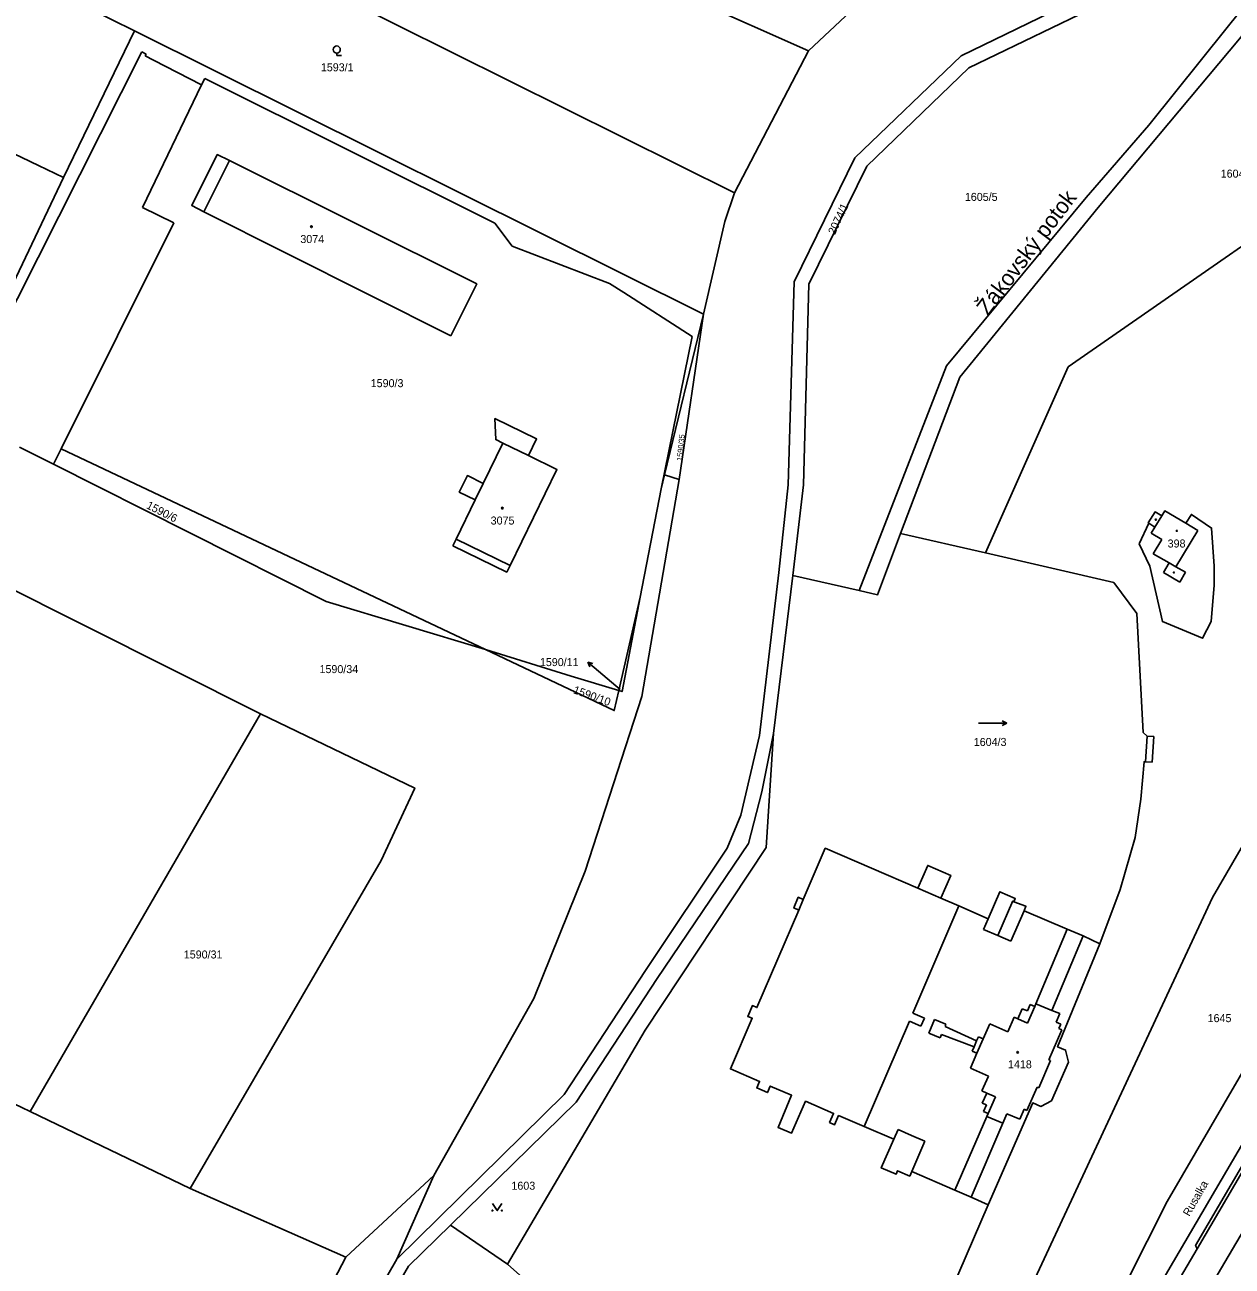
# Model space of a CAD drawing. Extents: x -679220 to -673243, y -1075091 to -1066557.
# Drawn here: x -677626.7 to -677370.2, y -1071876.4 to -1071612.6 of the extents above; entities that cross this region are included whole.
import ezdxf

# ---------------------------------------------------------------- set-up
doc = ezdxf.new("R2010")
doc.units = 0
for name, color, linetype in [('Hranice parcel', 7, 'Continuous'), ('Parcelní čísla', 7, 'Continuous'), ('Pop  PČ popisy', 7, 'Continuous'), ('Vnitřní kresba', 7, 'Continuous'), ('Značky budov', 7, 'Continuous'), ('Značky kultur', 7, 'Continuous')]:
    doc.layers.add(name, color=color, linetype=linetype)

msp = doc.modelspace()

# ---------------------------------------------------------------- linework, layer by layer
at = {"layer": 'Hranice parcel'}
for p, q in [((-677475.97, -1071648.33), (-677611.33, -1071580.93)), ((-677603.41, -1071613.91), (-677623.32, -1071603.99)), ((-677460.19, -1071618.11), (-677484.77, -1071607.17)), ((-677451.21, -1071609.71), (-677460.19, -1071618.11)), ((-677603.41, -1071613.91), (-677618.5, -1071645.05)), ((-677482.55, -1071674.1), (-677603.41, -1071613.91)), ((-677618.5, -1071645.05), (-677675.7, -1071617.62)), ((-677475.97, -1071648.33), (-677460.19, -1071618.11)), ((-677618.5, -1071645.05), (-677641.36, -1071692.91)), ((-677490.81, -1071708.2), (-677482.55, -1071674.1)), ((-677487.67, -1071709.23), (-677482.55, -1071674.1)), ((-677627.85, -1071702.34), (-677620.62, -1071705.96)), ((-677487.67, -1071709.23), (-677490.81, -1071708.2)), ((-677440.64, -1071720.72), (-677422.65, -1071724.8)), ((-677576.6, -1071759.04), (-677642.42, -1071725.99)), ((-677463.55, -1071729.64), (-677467.68, -1071763.17)), ((-677449.46, -1071732.84), (-677463.55, -1071729.64)), ((-677500.52, -1071754.07), (-677495.95, -1071734.2)), ((-677576.6, -1071759.04), (-677625.55, -1071843.55)), ((-677625.55, -1071843.55), (-677690.35, -1071812.12)), ((-677591.59, -1071859.9), (-677625.55, -1071843.55)), ((-677388.37, -1071885.06), (-677364.82, -1071844.92)), ((-677539.81, -1071857.13), (-677558.48, -1071874.5)), ((-677547.65, -1071874.9), (-677539.81, -1071857.13)), ((-677558.48, -1071874.5), (-677591.59, -1071859.9)), ((-677536.24, -1071867.65), (-677524.13, -1071875.98))]:
    msp.add_line(p, q, dxfattribs=at)
for points in [[(-677547.65, -1071874.9), (-677512.13, -1071839.9), (-677494.84, -1071813.59), (-677477.52, -1071787.54), (-677474.59, -1071780.52), (-677470.62, -1071763.59), (-677466.53, -1071728.98), (-677464.55, -1071710.33), (-677463.26, -1071667.2), (-677450.4, -1071640.86), (-677427.79, -1071619.2), (-677404.1, -1071607.74), (-677392.74, -1071599.33), (-677364.3, -1071568.01), (-677352.33, -1071547.38), (-677353.42, -1071517.27), (-677364.45, -1071472.8), (-677366.9, -1071460.72), (-677361.99, -1071451.74), (-677335.82, -1071408.46), (-677315.48, -1071374.36), (-677305.32, -1071362.98)], [(-677361.41, -1071471.95), (-677350.43, -1071516.86), (-677349.56, -1071533.03), (-677349.29, -1071547.83), (-677361.83, -1071569.86), (-677390.7, -1071601.66), (-677402.66, -1071610.43), (-677426.13, -1071621.73), (-677447.8, -1071642.64), (-677460.12, -1071667.74), (-677461.31, -1071710.35), (-677463.55, -1071729.64)], [(-677449.46, -1071732.84), (-677430.89, -1071685.08), (-677401.23, -1071649.29), (-677387.93, -1071633.95), (-677371.26, -1071613.2), (-677344.18, -1071579.41), (-677335.48, -1071540.9), (-677322.24, -1071482.13)], [(-677337.68, -1071566.95), (-677341.37, -1071581.96), (-677368.67, -1071615.55), (-677398.69, -1071651.4), (-677428.04, -1071687.44), (-677440.64, -1071720.72)], [(-677422.65, -1071724.8), (-677405.05, -1071685.3), (-677334.85, -1071636.58), (-677327.31, -1071627.01)], [(-677536.2, -1071678.67), (-677588.68, -1071652.34), (-677591.25, -1071651), (-677585.84, -1071640.17), (-677583.21, -1071641.44), (-677530.69, -1071667.67), (-677536.2, -1071678.67)], [(-677482.55, -1071674.1), (-677478.02, -1071654.43), (-677475.97, -1071648.33)], [(-677535.78, -1071723.31), (-677535.1, -1071721.91), (-677531.01, -1071713.55), (-677534.43, -1071711.88), (-677532.67, -1071708.39), (-677529.3, -1071710.04), (-677525.13, -1071701.5), (-677526.66, -1071700.75), (-677526.82, -1071696.29), (-677518, -1071700.6), (-677519.73, -1071704.13), (-677513.66, -1071707.1), (-677523.63, -1071727.51), (-677524.31, -1071728.91), (-677535.78, -1071723.31)], [(-677620.62, -1071705.96), (-677618.98, -1071702.68), (-677528.86, -1071745.38)], [(-677620.62, -1071705.96), (-677562.65, -1071735.14), (-677528.86, -1071745.38)], [(-677539.81, -1071857.13), (-677518.6, -1071819.49), (-677507.69, -1071792.48), (-677495.6, -1071755.32), (-677487.67, -1071709.23)], [(-677495.95, -1071734.2), (-677491.54, -1071711.22), (-677490.81, -1071708.2)], [(-677389.96, -1071722.91), (-677387.74, -1071727.63), (-677385.04, -1071739.4), (-677376.49, -1071742.94), (-677374.66, -1071739.36), (-677374.06, -1071731.64), (-677374.05, -1071727.62), (-677374.6, -1071719.54), (-677378.88, -1071716.64), (-677380.07, -1071718.51), (-677384.53, -1071715.89), (-677385.16, -1071716.93), (-677386.58, -1071716.1), (-677388.04, -1071718.46), (-677387.94, -1071718.52), (-677389.96, -1071722.91)], [(-677440.64, -1071720.72), (-677445.56, -1071733.72), (-677449.46, -1071732.84)], [(-677398.31, -1071807.87), (-677394.02, -1071796.32), (-677390.81, -1071785.3), (-677389.64, -1071777.13), (-677388.92, -1071769.19), (-677388.63, -1071769.2), (-677388.25, -1071763.76), (-677389.12, -1071762.96), (-677390.46, -1071737.69), (-677395.38, -1071731.13), (-677422.65, -1071724.8)], [(-677495.95, -1071734.2), (-677499.82, -1071754.28), (-677500.52, -1071754.07)], [(-677429.99, -1071917.37), (-677374.41, -1071798.07), (-677357.92, -1071769.61), (-677336.34, -1071740.8)], [(-677528.86, -1071745.38), (-677501.5, -1071758.34), (-677500.52, -1071754.07)], [(-677528.86, -1071745.38), (-677510.63, -1071750.99), (-677500.52, -1071754.07)], [(-677319.11, -1071756.26), (-677333.59, -1071777.09), (-677353.45, -1071810.1), (-677384.02, -1071862.66), (-677396.73, -1071887.8), (-677406.87, -1071911.8), (-677407.41, -1071916.34)], [(-677591.59, -1071859.9), (-677551.02, -1071790.19), (-677543.85, -1071774.81), (-677576.6, -1071759.04)], [(-677467.68, -1071763.17), (-677470.11, -1071775.61), (-677472.96, -1071786.54), (-677492.39, -1071815.25), (-677509.58, -1071841.54), (-677536.24, -1071867.65)], [(-677524.13, -1071875.98), (-677494.9, -1071826.26), (-677469.21, -1071787.42), (-677467.68, -1071763.17)], [(-677398.31, -1071807.87), (-677401.9, -1071806.2), (-677405.29, -1071804.76), (-677414.42, -1071800.86), (-677414.02, -1071799.92), (-677416.57, -1071798.97), (-677416.29, -1071798.24), (-677419.54, -1071796.82), (-677422.06, -1071802.6), (-677428.26, -1071799.84), (-677432.11, -1071798.18), (-677430.01, -1071793.36), (-677434.9, -1071791.21), (-677437, -1071796.07), (-677456.66, -1071787.59), (-677461.32, -1071798.45), (-677462.39, -1071797.99), (-677463.36, -1071800.25), (-677462.29, -1071800.7), (-677471.19, -1071821.43), (-677472.13, -1071821.02), (-677473.11, -1071823.31), (-677472.17, -1071823.71), (-677476.8, -1071834.48), (-677470.62, -1071837.14), (-677471.22, -1071838.51), (-677468.93, -1071839.49), (-677468.34, -1071838.12), (-677463.8, -1071840.08), (-677466.68, -1071846.9), (-677463.83, -1071848.13), (-677460.85, -1071841.35), (-677454.9, -1071843.92), (-677455.74, -1071845.83), (-677454.67, -1071846.32), (-677453.83, -1071844.38), (-677448.4, -1071846.72), (-677442.06, -1071849.38), (-677444.77, -1071855.51), (-677441.6, -1071856.84), (-677441.28, -1071856.12), (-677438.72, -1071857.23), (-677438.3, -1071856.27), (-677429.1, -1071860.26), (-677425.69, -1071861.73), (-677422.03, -1071863.33)], [(-677422.03, -1071863.33), (-677412.57, -1071841.7), (-677410.84, -1071842.45), (-677408.59, -1071841.23), (-677405, -1071833.07), (-677405.59, -1071830.46), (-677407.32, -1071829.75), (-677398.31, -1071807.87)], [(-677362.83, -1071846.09), (-677378, -1071871.97), (-677377.64, -1071872.67)], [(-677377.64, -1071872.67), (-677366.73, -1071854.04), (-677361.12, -1071857.35), (-677362.14, -1071859.08), (-677349.2, -1071866.71), (-677350.73, -1071869.37), (-677348.57, -1071870.58), (-677352.24, -1071876.83), (-677354.18, -1071875.7), (-677359.9, -1071885.41), (-677365.52, -1071882.11), (-677358.68, -1071870.47), (-677366.2, -1071866.05), (-677374.1, -1071879.52)], [(-677446.61, -1071915.3), (-677431.42, -1071885.01), (-677422.03, -1071863.33)], [(-677536.24, -1071867.65), (-677545.18, -1071876.41), (-677551.26, -1071886.91), (-677551.95, -1071896.52), (-677549, -1071898.42), (-677557.64, -1071899.41)], [(-677374.1, -1071879.52), (-677376.27, -1071883.23), (-677381.89, -1071879.93), (-677377.64, -1071872.67)], [(-677558.48, -1071874.5), (-677562.8, -1071882.76), (-677569.64, -1071895.54), (-677576, -1071917.67)], [(-677557.64, -1071899.41), (-677554, -1071885.85), (-677547.65, -1071874.9)], [(-677446.61, -1071915.3), (-677488.59, -1071898.31), (-677490.88, -1071897.09), (-677520.24, -1071879.43), (-677524.13, -1071875.98)]]:
    msp.add_lwpolyline(points, dxfattribs=at)
at = {"layer": 'Pop  PČ popisy'}
for p, q in [((-677504.8, -1071749.96), (-677507.1, -1071748.03)), ((-677507.1, -1071748.03), (-677506.01, -1071748.29)), ((-677507.1, -1071748.03), (-677506.65, -1071749.06)), ((-677500.22, -1071753.85), (-677504.8, -1071749.96))]:
    msp.add_line(p, q, dxfattribs=at)
at = {"layer": 'Vnitřní kresba'}
for p, q in [((-677601.83, -1071618.35), (-677639.79, -1071693.55)), ((-677600.95, -1071618.81), (-677601.83, -1071618.35)), ((-677601.13, -1071619.17), (-677600.95, -1071618.81)), ((-677599.35, -1071620.09), (-677601.13, -1071619.17)), ((-677589.14, -1071625.39), (-677599.35, -1071620.09)), ((-677589.14, -1071625.39), (-677601.68, -1071651.45)), ((-677588.49, -1071624.04), (-677589.14, -1071625.39)), ((-677526.82, -1071654.76), (-677588.49, -1071624.04)), ((-677588.68, -1071652.34), (-677583.21, -1071641.44)), ((-677601.68, -1071651.45), (-677595.02, -1071654.66)), ((-677595.02, -1071654.66), (-677618.98, -1071702.68)), ((-677523.19, -1071659.61), (-677526.82, -1071654.76)), ((-677502.49, -1071667.57), (-677523.19, -1071659.61)), ((-677499.45, -1071669.45), (-677502.49, -1071667.57)), ((-677484.96, -1071678.85), (-677499.45, -1071669.45)), ((-677484.96, -1071678.85), (-677491.54, -1071711.22)), ((-677525.13, -1071701.5), (-677519.73, -1071704.13)), ((-677529.3, -1071710.04), (-677531.01, -1071713.55)), ((-677386.62, -1071719.33), (-677385.16, -1071716.93)), ((-677387.94, -1071718.52), (-677386.62, -1071719.33)), ((-677386.62, -1071719.33), (-677387.41, -1071720.62)), ((-677387.41, -1071720.62), (-677385.15, -1071721.99)), ((-677382.2, -1071727.77), (-677377.48, -1071720.03)), ((-677380.07, -1071718.51), (-677377.48, -1071720.03)), ((-677535.1, -1071721.91), (-677523.63, -1071727.51)), ((-677385.15, -1071721.99), (-677386.97, -1071725.03)), ((-677383.62, -1071726.95), (-677386.97, -1071725.03)), ((-677384.83, -1071729), (-677383.62, -1071726.95)), ((-677382.2, -1071727.77), (-677383.62, -1071726.95)), ((-677380.1, -1071728.93), (-677382.2, -1071727.77)), ((-677381.35, -1071731.05), (-677384.83, -1071729)), ((-677380.1, -1071728.93), (-677381.35, -1071731.05)), ((-677388.25, -1071763.76), (-677386.84, -1071763.86)), ((-677386.84, -1071763.86), (-677387.22, -1071769.26)), ((-677387.22, -1071769.26), (-677388.63, -1071769.2)), ((-677437, -1071796.07), (-677432.11, -1071798.18)), ((-677461.32, -1071798.45), (-677462.29, -1071800.7)), ((-677420.01, -1071806.14), (-677416.82, -1071798.75)), ((-677416.82, -1071798.75), (-677416.57, -1071798.97)), ((-677428.26, -1071799.84), (-677438.05, -1071822.62)), ((-677417.21, -1071807.33), (-677414.42, -1071800.86)), ((-677422.06, -1071802.6), (-677423.04, -1071804.85)), ((-677423.04, -1071804.85), (-677420.01, -1071806.14)), ((-677405.29, -1071804.76), (-677411.9, -1071820.66)), ((-677420.01, -1071806.14), (-677417.21, -1071807.33)), ((-677401.9, -1071806.2), (-677408.51, -1071822.03)), ((-677413.11, -1071820.78), (-677413.71, -1071822.16)), ((-677412.13, -1071821.2), (-677413.11, -1071820.78)), ((-677411.9, -1071820.66), (-677412.13, -1071821.2)), ((-677411.9, -1071820.66), (-677408.51, -1071822.03)), ((-677438.05, -1071822.62), (-677435.58, -1071823.68)), ((-677417.9, -1071826.62), (-677416.53, -1071823.49)), ((-677415.75, -1071823.83), (-677416.53, -1071823.49)), ((-677414.82, -1071821.67), (-677415.75, -1071823.83)), ((-677413.71, -1071822.16), (-677414.82, -1071821.67)), ((-677412.13, -1071821.2), (-677413.67, -1071824.73)), ((-677408.51, -1071822.03), (-677406.86, -1071822.7)), ((-677406.86, -1071822.7), (-677407.59, -1071824.53)), ((-677438.79, -1071824.34), (-677448.4, -1071846.72)), ((-677436.32, -1071825.4), (-677438.79, -1071824.34)), ((-677435.58, -1071823.68), (-677436.32, -1071825.4)), ((-677434.69, -1071826.87), (-677433.45, -1071823.98)), ((-677433.45, -1071823.98), (-677431.03, -1071824.97)), ((-677431.03, -1071824.97), (-677431.22, -1071825.43)), ((-677431.22, -1071825.43), (-677424.5, -1071828.51)), ((-677423.11, -1071828.09), (-677421.72, -1071824.89)), ((-677421.72, -1071824.89), (-677417.9, -1071826.62)), ((-677413.67, -1071824.73), (-677415.75, -1071823.83)), ((-677407.59, -1071824.53), (-677406.62, -1071824.95)), ((-677406.62, -1071824.95), (-677407.03, -1071825.9)), ((-677407.03, -1071825.9), (-677406.39, -1071826.18)), ((-677432.26, -1071827.89), (-677434.69, -1071826.87)), ((-677431.97, -1071827.19), (-677432.26, -1071827.89)), ((-677425.05, -1071829.77), (-677431.97, -1071827.19)), ((-677425.05, -1071829.77), (-677424.5, -1071828.51)), ((-677424.5, -1071828.51), (-677424.13, -1071827.65)), ((-677424.43, -1071831.13), (-677423.11, -1071828.09)), ((-677424.13, -1071827.65), (-677423.11, -1071828.09)), ((-677406.39, -1071826.18), (-677409.16, -1071832.56)), ((-677425.82, -1071834.33), (-677424.43, -1071831.13)), ((-677425.45, -1071830.69), (-677425.05, -1071829.77)), ((-677424.43, -1071831.13), (-677425.45, -1071830.69)), ((-677408.79, -1071832.71), (-677411.3, -1071838.49)), ((-677409.16, -1071832.56), (-677408.79, -1071832.71)), ((-677422.01, -1071835.99), (-677425.82, -1071834.33)), ((-677423.39, -1071839.15), (-677422.01, -1071835.99)), ((-677422.36, -1071839.6), (-677423.39, -1071839.15)), ((-677411.67, -1071838.33), (-677413.82, -1071843.27)), ((-677411.3, -1071838.49), (-677411.67, -1071838.33)), ((-677423.29, -1071841.72), (-677422.36, -1071839.6)), ((-677422.41, -1071842.11), (-677423.29, -1071841.72)), ((-677420.49, -1071840.42), (-677422.36, -1071839.6)), ((-677422.04, -1071843.96), (-677420.49, -1071840.42)), ((-677422.33, -1071844.61), (-677429.1, -1071860.26)), ((-677423.03, -1071843.53), (-677422.41, -1071842.11)), ((-677422.04, -1071843.96), (-677423.03, -1071843.53)), ((-677422.33, -1071844.61), (-677422.04, -1071843.96)), ((-677418.92, -1071846.03), (-677422.33, -1071844.61)), ((-677418.92, -1071846.03), (-677418.05, -1071844.01)), ((-677418.05, -1071844.01), (-677415.34, -1071845.17)), ((-677414.43, -1071843), (-677415.34, -1071845.17)), ((-677413.82, -1071843.27), (-677414.43, -1071843)), ((-677425.69, -1071861.73), (-677418.92, -1071846.03)), ((-677442.06, -1071849.38), (-677441.15, -1071847.31)), ((-677441.15, -1071847.31), (-677438.32, -1071848.61)), ((-677435.53, -1071849.84), (-677438.32, -1071848.61)), ((-677438.3, -1071856.27), (-677435.53, -1071849.84))]:
    msp.add_line(p, q, dxfattribs=at)
at = {"layer": 'Značky budov'}
for centre, radius in [((-677565.81, -1071655.5), 0.175), ((-677525.25, -1071715.31), 0.175), ((-677386.43, -1071717.76), 0.117), ((-677381.98, -1071720.14), 0.117), ((-677382.59, -1071728.98), 0.117), ((-677415.8, -1071830.93), 0.175)]:
    msp.add_circle(centre, radius, dxfattribs=at)
at = {"layer": 'Značky kultur'}
for p, q in [((-677560.43, -1071618.6), (-677560.43, -1071619.1)), ((-677560.43, -1071619.1), (-677559.43, -1071619.1)), ((-677424.1, -1071761), (-677418.1, -1071761)), ((-677418.1, -1071761), (-677419.08, -1071760.5)), ((-677418.1, -1071761), (-677419.08, -1071761.5))]:
    msp.add_line(p, q, dxfattribs=at)
msp.add_lwpolyline([(-677527.35, -1071863.07), (-677526.35, -1071864.57), (-677525.35, -1071863.07)], dxfattribs=at)
for centre, radius in [((-677560.43, -1071617.85), 0.75), ((-677527.35, -1071864.57), 0.1), ((-677525.35, -1071864.57), 0.1)]:
    msp.add_circle(centre, radius, dxfattribs=at)

# ---------------------------------------------------------------- texts
at = {"layer": 'Parcelní čísla'}
for s, p in [('1593/1', (-677563.81, -1071622.48)), ('1604/1', (-677372.65, -1071645.07)), ('1605/5', (-677427, -1071650.02)), ('3074', (-677568.17, -1071658.98)), ('1590/3', (-677553.22, -1071689.6)), ('3075', (-677527.74, -1071718.79)), ('398', (-677383.92, -1071723.67)), ('1590/34', (-677564.1, -1071750.36)), ('1590/11', (-677517.28, -1071748.87)), ('1604/3', (-677425.11, -1071765.84)), ('1590/31', (-677592.93, -1071811)), ('1645', (-677375.43, -1071824.53)), ('1418', (-677417.84, -1071834.34)), ('1603', (-677523.33, -1071860.14))]:
    msp.add_text(s, height=1.7, dxfattribs=at).set_placement(p)
for s, height, rotation, p in [('2074/1', 1.7, 65, (-677454.62, -1071657.34)), ('1590/35', 1.14, 84, (-677487.1, -1071705.34)), ('1590/6', 1.7, 333, (-677601.04, -1071715.25)), ('1590/10', 1.7, 340, (-677510.35, -1071754.59))]:
    msp.add_text(s, height=height, rotation=rotation, dxfattribs=at).set_placement(p)
at = {"layer": 'Pop  PČ popisy'}
for s, height, rotation, p in [('Žákovský potok', 3.4, 53, (-677422.1, -1071674.6)), ('Rusalka', 1.7, 60, (-677379.32, -1071865.93))]:
    msp.add_text(s, height=height, rotation=rotation, dxfattribs=at).set_placement(p)

doc.saveas('drawing.dxf')
